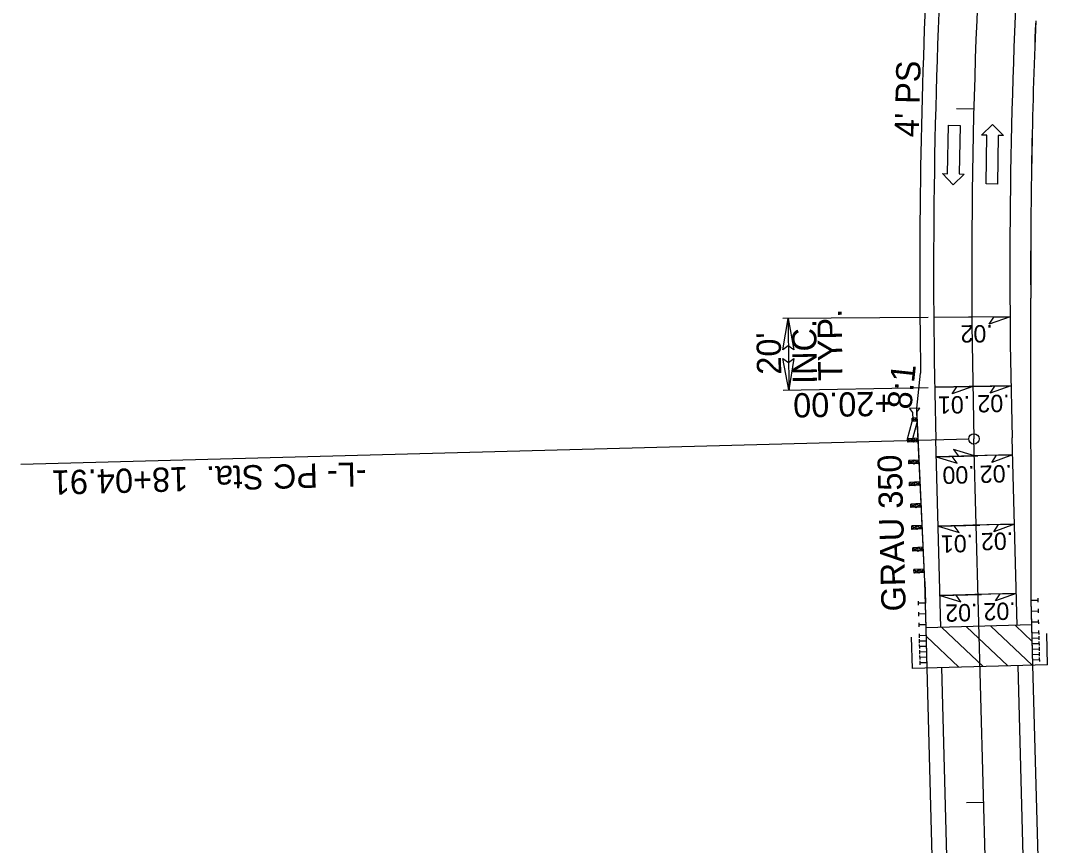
# Model space of a CAD drawing. Extents: x 1835351 to 1836442, y 993887 to 995358.
# Drawn here: x 1835606.9 to 1835906.4, y 994645.1 to 994882.9 of the extents above; entities that cross this region are included whole.
import ezdxf

# ---------------------------------------------------------------- set-up
doc = ezdxf.new("R2010")
doc.units = 0
for name, color, linetype in [('Prop Approach Slab', 7, 'Continuous'), ('Prop Approach Slab Hatching', 7, 'Continuous'), ('Prop Dimension', 7, 'Continuous'), ('Prop Dimension Text', 7, 'Continuous'), ('Prop EOT', 7, 'Continuous'), ('Prop Guardrail', 7, 'Continuous'), ('Prop Guardrail Anchor Unit CELL', 7, 'Continuous'), ('Prop Horizontal Alignment', 7, 'Continuous'), ('Prop Horizontal Alignment Station Label', 7, 'Continuous'), ('Prop Horizontal Alignment Tick Small', 7, 'Continuous'), ('Prop Lane Arrow CELL', 7, 'Continuous'), ('Prop Lane Lines', 7, 'Continuous'), ('Prop Paved Shoulder', 7, 'Continuous'), ('Prop Roadway Bridge', 7, 'Continuous'), ('Prop Structure Anchor Unit CELL', 7, 'Continuous'), ('Prop Superelevation  Arrow CELL', 7, 'Continuous'), ('Prop Superelevation Label', 7, 'Continuous'), ('Prop Terminator CELL', 7, 'Continuous')]:
    doc.layers.add(name, color=color, linetype=linetype)

msp = doc.modelspace()

# ---------------------------------------------------------------- linework, layer by layer
at = {"layer": 'Prop Approach Slab'}
for p, q in [((1835898.48, 994708.64), (1835867.99, 994707.83)), ((1835868.3, 994696.21), (1835867.99, 994707.83)), ((1835898.79, 994697.03), (1835898.48, 994708.64))]:
    msp.add_line(p, q, dxfattribs=at)
at = {"layer": 'Prop Approach Slab Hatching'}
for p, q in [((1835872.53, 994707.95), (1835884.47, 994696.65)), ((1835879.6, 994708.14), (1835891.54, 994696.83)), ((1835886.68, 994708.33), (1835898.61, 994697.02)), ((1835893.75, 994708.52), (1835898.6, 994703.92)), ((1835868.06, 994705.3), (1835877.4, 994696.46))]:
    msp.add_line(p, q, dxfattribs=at)
at = {"layer": 'Prop Dimension'}
for p, q in [((1835868.53, 994797.31), (1835826.69, 994797)), ((1835826.77, 994776.4), (1835868.53, 994777.17))]:
    msp.add_line(p, q, dxfattribs=at)
msp.add_arc((1837691.14, 994810.76), 1863.01, 180.42293, 181.05603, dxfattribs=at)
at = {"layer": 'Prop EOT'}
for p, q in [((1835872.24, 994707.94), (1835870.79, 994762.02)), ((1835894.23, 994708.53), (1835892.78, 994762.61))]:
    msp.add_line(p, q, dxfattribs=at)
for radius in [1821, 1799]:
    msp.add_arc((1837691.14, 994810.76), radius, 176.94086, 181.53384, dxfattribs=at)
at = {"layer": 'Prop Guardrail'}
for p, q in [((1835898.29, 994715.77), (1835898.15, 994802.92)), ((1835867.63, 994721.2), (1835867.8, 994714.96))]:
    msp.add_line(p, q, dxfattribs=at)
msp.add_arc((1837691.14, 994810.76), 1793, 177.69413, 180.25074, dxfattribs=at)
at = {"layer": 'Prop Guardrail Anchor Unit CELL'}
for p, q in [((1835866.14, 994771.18), (1835863.2, 994771.1)), ((1835863.2, 994771.1), (1835864.09, 994769.94)), ((1835865.31, 994769.98), (1835866.14, 994771.18)), ((1835865.42, 994768.4), (1835863.92, 994768.33)), ((1835863.97, 994767.33), (1835863.92, 994768.33)), ((1835863.92, 994768.33), (1835865.47, 994767.4)), ((1835863.97, 994767.33), (1835863.95, 994767.83)), ((1835865.42, 994768.4), (1835863.97, 994767.33)), ((1835865.47, 994767.4), (1835863.97, 994767.33)), ((1835864.09, 994769.94), (1835864.15, 994767.9)), ((1835864.15, 994767.9), (1835864.76, 994767.91)), ((1835864.17, 994762.44), (1835865.47, 994767.4)), ((1835864.76, 994767.91), (1835865.37, 994767.93)), ((1835865.37, 994767.93), (1835865.31, 994769.98)), ((1835867.63, 994721.2), (1835865.44, 994767.9)), ((1835862.64, 994762.37), (1835863.97, 994767.33)), ((1835865.7, 994762.51), (1835862.64, 994762.37)), ((1835862.68, 994761.37), (1835862.64, 994762.37)), ((1835862.64, 994762.37), (1835864.21, 994761.44)), ((1835864.17, 994762.44), (1835862.68, 994761.37)), ((1835865.74, 994761.51), (1835862.68, 994761.37)), ((1835864.21, 994761.44), (1835864.17, 994762.44)), ((1835865.74, 994761.51), (1835864.17, 994762.44)), ((1835864.21, 994761.44), (1835865.7, 994762.51)), ((1835865.99, 994756.21), (1835862.99, 994756.07)), ((1835863.04, 994755.07), (1835862.99, 994756.07)), ((1835862.99, 994756.07), (1835864.54, 994755.14)), ((1835864.49, 994756.14), (1835863.04, 994755.07)), ((1835864.54, 994755.14), (1835864.49, 994756.14)), ((1835866.04, 994755.22), (1835864.49, 994756.14)), ((1835864.54, 994755.14), (1835865.99, 994756.21)), ((1835866.04, 994755.22), (1835863.04, 994755.07)), ((1835866.29, 994749.92), (1835863.15, 994749.77)), ((1835863.2, 994748.77), (1835863.15, 994749.77)), ((1835863.15, 994749.77), (1835864.77, 994748.85)), ((1835864.72, 994749.85), (1835863.2, 994748.77)), ((1835864.77, 994748.85), (1835864.72, 994749.85)), ((1835866.33, 994748.92), (1835864.72, 994749.85)), ((1835864.77, 994748.85), (1835866.29, 994749.92)), ((1835866.33, 994748.92), (1835863.2, 994748.77)), ((1835866.58, 994743.63), (1835863.55, 994743.48)), ((1835863.59, 994742.48), (1835863.55, 994743.48)), ((1835863.55, 994743.48), (1835865.11, 994742.56)), ((1835865.06, 994743.55), (1835863.59, 994742.48)), ((1835865.11, 994742.56), (1835865.06, 994743.55)), ((1835866.63, 994742.63), (1835865.06, 994743.55)), ((1835865.11, 994742.56), (1835866.58, 994743.63)), ((1835866.63, 994742.63), (1835866.58, 994743.63)), ((1835866.63, 994742.63), (1835863.59, 994742.48)), ((1835866.87, 994737.33), (1835863.83, 994737.19)), ((1835863.88, 994736.19), (1835863.83, 994737.19)), ((1835863.83, 994737.19), (1835865.4, 994736.26)), ((1835865.35, 994737.26), (1835863.88, 994736.19)), ((1835866.92, 994736.33), (1835863.88, 994736.19)), ((1835865.4, 994736.26), (1835865.35, 994737.26)), ((1835866.92, 994736.33), (1835865.35, 994737.26)), ((1835865.4, 994736.26), (1835866.87, 994737.33)), ((1835867.17, 994731.04), (1835864.12, 994730.89)), ((1835864.17, 994729.89), (1835864.12, 994730.89)), ((1835864.12, 994730.89), (1835865.69, 994729.97)), ((1835865.64, 994730.97), (1835864.17, 994729.89)), ((1835867.22, 994730.04), (1835864.17, 994729.89)), ((1835865.69, 994729.97), (1835865.64, 994730.97)), ((1835867.22, 994730.04), (1835865.64, 994730.97)), ((1835865.69, 994729.97), (1835867.17, 994731.04)), ((1835867.46, 994724.74), (1835864.47, 994724.6)), ((1835864.51, 994723.6), (1835864.47, 994724.6)), ((1835864.47, 994724.6), (1835866.01, 994723.67)), ((1835865.97, 994724.67), (1835864.51, 994723.6)), ((1835867.51, 994723.74), (1835864.51, 994723.6)), ((1835867.46, 994724.74), (1835865.97, 994724.67)), ((1835866.01, 994723.67), (1835865.97, 994724.67)), ((1835865.97, 994724.67), (1835867.51, 994723.74)), ((1835866.01, 994723.67), (1835867.46, 994724.74)), ((1835867.51, 994723.74), (1835867.46, 994724.74))]:
    msp.add_line(p, q, dxfattribs=at)
at = {"layer": 'Prop Horizontal Alignment'}
msp.add_line((1835893.09, 994340.01), (1835881.78, 994762.31), dxfattribs=at)
msp.add_arc((1837691.14, 994810.76), 1810, 170.42027, 181.53384, dxfattribs=at)
at = {"layer": 'Prop Horizontal Alignment Station Label'}
msp.add_line((1835880.28, 994762.27), (1835606.88, 994754.95), dxfattribs=at)
msp.add_circle((1835881.78, 994762.31), 1.5, dxfattribs=at)
at = {"layer": 'Prop Horizontal Alignment Tick Small'}
for p, q in [((1835881.74, 994857.4), (1835876.74, 994857.53)), ((1835881.92, 994757.41), (1835876.92, 994757.28)), ((1835884.59, 994657.44), (1835879.59, 994657.31))]:
    msp.add_line(p, q, dxfattribs=at)
at = {"layer": 'Prop Lane Arrow CELL'}
for p, q in [((1835874.18, 994838.8), (1835874.46, 994852.79)), ((1835874.46, 994852.79), (1835877.76, 994852.72)), ((1835877.76, 994852.72), (1835877.48, 994838.73)), ((1835883.97, 994849.89), (1835887.11, 994853)), ((1835887.11, 994853), (1835890.26, 994849.8)), ((1835885.47, 994849.87), (1835883.97, 994849.89)), ((1835885.26, 994835.87), (1835885.47, 994849.87)), ((1835888.76, 994849.82), (1835888.56, 994835.82)), ((1835890.26, 994849.8), (1835888.76, 994849.82)), ((1835875.81, 994835.61), (1835872.68, 994838.83)), ((1835872.68, 994838.83), (1835874.18, 994838.8)), ((1835878.97, 994838.7), (1835875.81, 994835.61)), ((1835877.48, 994838.73), (1835878.97, 994838.7)), ((1835888.56, 994835.82), (1835885.26, 994835.87))]:
    msp.add_line(p, q, dxfattribs=at)
at = {"layer": 'Prop Paved Shoulder'}
for p, q in [((1835898.29, 994715.77), (1835898.15, 994802.92)), ((1835865.29, 994771.15), (1835866.37, 994781.27)), ((1835867.63, 994721.2), (1835865.29, 994771.15)), ((1835867.99, 994707.83), (1835867.63, 994721.2)), ((1835898.48, 994708.64), (1835898.29, 994715.77))]:
    msp.add_line(p, q, dxfattribs=at)
for centre, radius, start, end in [((1837691.14, 994810.76), 1825, 176.94086, 180.92604), ((1837680.42, 994810.95), 1782.29, 177.68644, 180.25842)]:
    msp.add_arc(centre, radius, start, end, dxfattribs=at)
at = {"layer": 'Prop Roadway Bridge'}
for p, q in [((1835864.05, 994696.1), (1835863.8, 994705.1)), ((1835903.04, 994697.14), (1835902.79, 994706.14)), ((1835903.04, 994697.14), (1835864.05, 994696.1)), ((1835873.45, 994503.9), (1835868.3, 994696.21)), ((1835877.7, 994504.02), (1835872.55, 994696.33)), ((1835899.69, 994504.6), (1835894.54, 994696.92)), ((1835903.94, 994504.72), (1835898.79, 994697.03))]:
    msp.add_line(p, q, dxfattribs=at)
at = {"layer": 'Prop Structure Anchor Unit CELL'}
for p, q in [((1835865.81, 994714.33), (1835865.78, 994715.47)), ((1835867.8, 994714.96), (1835865.8, 994714.9)), ((1835868.3, 994696.21), (1835867.8, 994714.96)), ((1835898.29, 994715.77), (1835900.29, 994715.83)), ((1835898.79, 994697.03), (1835898.29, 994715.77)), ((1835900.3, 994715.25), (1835900.27, 994716.4)), ((1835865.9, 994711.21), (1835865.87, 994712.35)), ((1835867.88, 994711.83), (1835865.88, 994711.78)), ((1835898.37, 994712.65), (1835900.37, 994712.7)), ((1835900.38, 994712.13), (1835900.35, 994713.27)), ((1835865.98, 994708.08), (1835865.95, 994709.23)), ((1835867.96, 994708.71), (1835865.96, 994708.65)), ((1835898.45, 994709.52), (1835900.45, 994709.58)), ((1835900.47, 994709.01), (1835900.44, 994710.15)), ((1835866.06, 994704.96), (1835866.03, 994706.1)), ((1835868.05, 994705.58), (1835866.05, 994705.53)), ((1835866.11, 994703.4), (1835866.08, 994704.54)), ((1835898.54, 994706.4), (1835900.54, 994706.45)), ((1835898.58, 994704.84), (1835900.58, 994704.89)), ((1835900.55, 994705.88), (1835900.52, 994707.03)), ((1835900.59, 994704.32), (1835900.56, 994705.46)), ((1835868.09, 994704.02), (1835866.09, 994703.97)), ((1835866.15, 994701.83), (1835866.12, 994702.98)), ((1835868.13, 994702.46), (1835866.13, 994702.41)), ((1835898.62, 994703.28), (1835900.62, 994703.33)), ((1835898.66, 994701.71), (1835900.66, 994701.77)), ((1835900.64, 994702.76), (1835900.6, 994703.9)), ((1835900.68, 994701.2), (1835900.65, 994702.34)), ((1835866.19, 994700.27), (1835866.16, 994701.42)), ((1835868.17, 994700.9), (1835866.17, 994700.84)), ((1835866.23, 994698.71), (1835866.2, 994699.86)), ((1835868.22, 994699.34), (1835866.22, 994699.28)), ((1835898.7, 994700.15), (1835900.7, 994700.21)), ((1835898.75, 994698.59), (1835900.75, 994698.64)), ((1835900.72, 994699.63), (1835900.69, 994700.78)), ((1835900.76, 994698.07), (1835900.73, 994699.22)), ((1835866.27, 994697.15), (1835866.24, 994698.29)), ((1835868.26, 994697.77), (1835866.26, 994697.72))]:
    msp.add_line(p, q, dxfattribs=at)
at = {"layer": 'Prop Superelevation  Arrow CELL'}
for p, q in [((1835892.18, 994797.48), (1835880.19, 994797.39)), ((1835881.44, 994777.4), (1835870.45, 994777.2)), ((1835892.44, 994777.61), (1835880.44, 994777.38)), ((1835870.92, 994757.11), (1835882.92, 994757.44)), ((1835881.92, 994757.41), (1835870.92, 994757.11)), ((1835892.91, 994757.7), (1835880.92, 994757.38)), ((1835871.45, 994737.12), (1835883.45, 994737.44)), ((1835893.45, 994737.71), (1835881.45, 994737.39)), ((1835871.99, 994717.13), (1835883.99, 994717.45)), ((1835871.99, 994717.13), (1835883.99, 994717.45)), ((1835893.98, 994717.72), (1835881.99, 994717.4))]:
    msp.add_line(p, q, dxfattribs=at)
for points in [[(1835892.18, 994797.48), (1835886.2, 994795.44), (1835887.56, 994797.45)], [(1835881.44, 994777.4), (1835875.48, 994775.29), (1835876.82, 994777.32)], [(1835892.44, 994777.61), (1835886.48, 994775.5), (1835887.82, 994777.52)], [(1835881.92, 994757.41), (1835875.86, 994759.25), (1835877.29, 994757.29)], [(1835870.92, 994757.11), (1835876.97, 994755.28), (1835875.54, 994757.24)], [(1835892.91, 994757.7), (1835886.97, 994755.54), (1835888.29, 994757.58)], [(1835893.45, 994737.71), (1835887.5, 994735.55), (1835888.82, 994737.59)], [(1835871.45, 994737.12), (1835877.51, 994735.28), (1835876.08, 994737.25)], [(1835871.99, 994717.13), (1835878.04, 994715.29), (1835876.61, 994717.25)], [(1835871.99, 994717.13), (1835878.04, 994715.29), (1835876.61, 994717.25)], [(1835893.98, 994717.72), (1835888.04, 994715.56), (1835889.36, 994717.59)]]:
    msp.add_lwpolyline(points, close=True, dxfattribs=at)
at = {"layer": 'Prop Superelevation Label'}
for p, q in [((1835892.18, 994797.48), (1835870.19, 994797.32)), ((1835870.45, 994777.2), (1835892.44, 994777.61)), ((1835892.91, 994757.7), (1835870.92, 994757.11)), ((1835893.45, 994737.71), (1835871.45, 994737.12)), ((1835893.98, 994717.72), (1835871.99, 994717.13))]:
    msp.add_line(p, q, dxfattribs=at)
at = {"layer": 'Prop Terminator CELL'}
for points in [[(1835826.69, 994788), (1835828.17, 994797.01), (1835829.84, 994787.97), (1835828.23, 994789.11)], [(1835829.82, 994785.45), (1835828.44, 994776.43), (1835826.67, 994785.45), (1835828.29, 994784.32)]]:
    msp.add_lwpolyline(points, close=True, dxfattribs=at)

# ---------------------------------------------------------------- texts
at = {"layer": 'Prop Dimension Text'}
for s, rotation, p in [('TYP.', 90.7395, (1835843.89, 994779.04)), ('INC.', 90.7395, (1835836.52, 994778.2)), ("20'", 90.7395, (1835826.21, 994780.88)), ('+20.00', 181.056, (1835858.46, 994776))]:
    msp.add_text(s, height=7, rotation=rotation, dxfattribs=at).set_placement(p)
at = {"layer": 'Prop Guardrail Anchor Unit CELL'}
msp.add_text('GRAU 350', height=7, rotation=91.5643, dxfattribs=at).set_placement((1835862.14, 994712.63))
at = {"layer": 'Prop Horizontal Alignment Station Label'}
msp.add_text('-L- PC Sta.  18+04.91', height=7, rotation=181.5338, dxfattribs=at).set_placement((1835706.53, 994755.62))
at = {"layer": 'Prop Lane Lines'}
for s, rotation, p in [('.02', 180.4229, (1835887.18, 994795.16)), ('.01', 181.056, (1835880.65, 994774.72)), ('.02', 181.056, (1835892.03, 994775.11)), ('.00', 181.5338, (1835881.93, 994754.53)), ('.02', 181.5338, (1835892.69, 994754.83)), ('.01', 181.5338, (1835881.48, 994734.7)), ('.02', 181.5338, (1835893.03, 994735.4)), ('.02', 181.5338, (1835882.74, 994714.79)), ('.02', 181.5338, (1835893.77, 994715.19))]:
    msp.add_text(s, height=5, rotation=rotation, dxfattribs=at).set_placement(p)
at = {"layer": 'Prop Terminator CELL'}
for s, rotation, p in [("4' PS", 88.5842, (1835865.87, 994849.26)), ('8:1', 83.8907, (1835863.68, 994770.61))]:
    msp.add_text(s, height=7, rotation=rotation, dxfattribs=at).set_placement(p)

doc.saveas('drawing.dxf')
